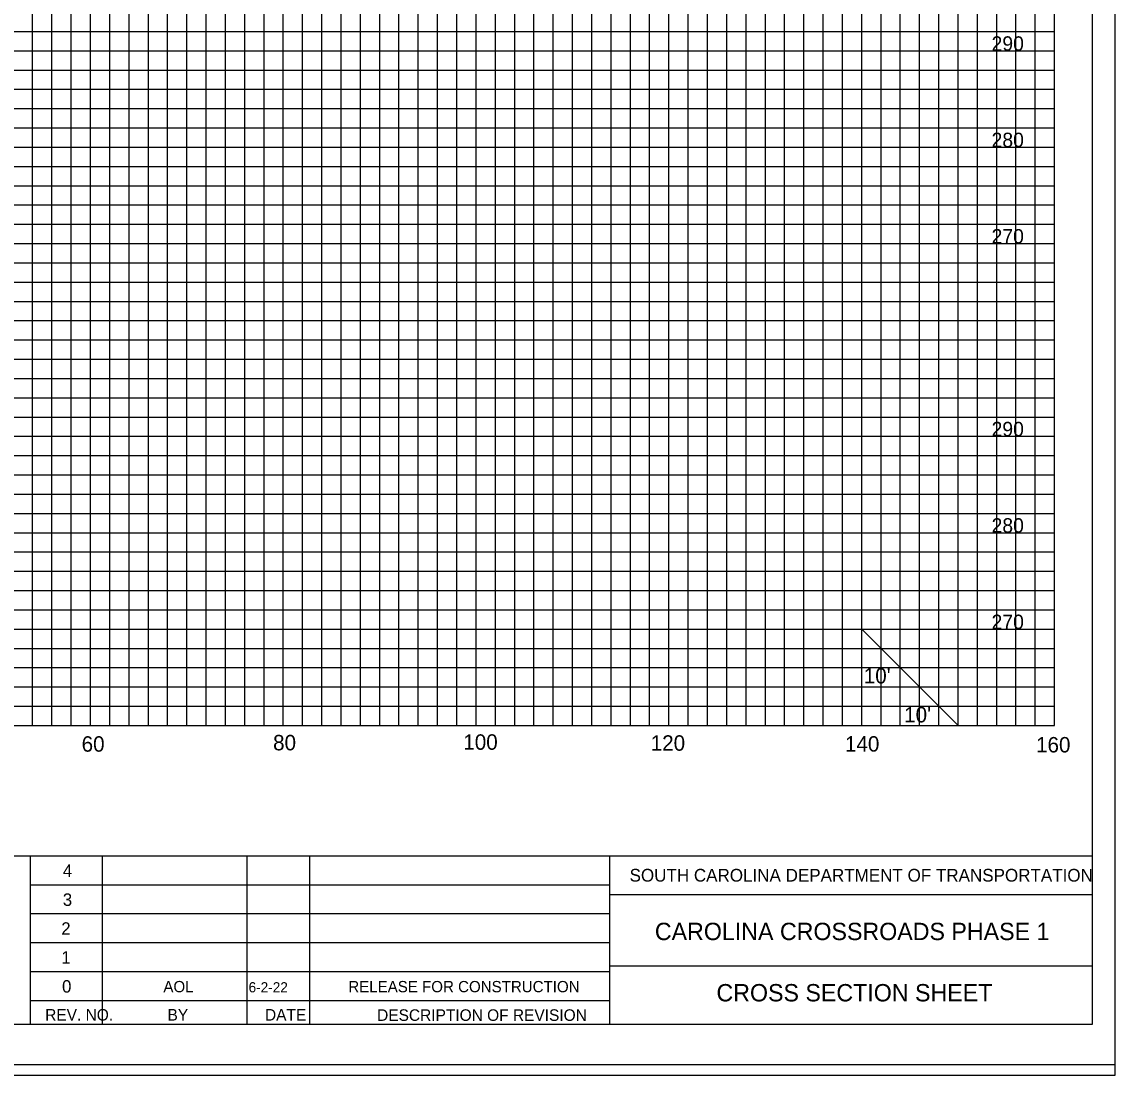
# Model space of a CAD drawing. Extents: x 967 to 1326, y 964 to 3704.
# Drawn here: x 1212.9 to 1326.3, y 2083.7 to 2193 of the extents above; entities that cross this region are included whole.
import ezdxf

# ---------------------------------------------------------------- set-up
doc = ezdxf.new("R2010")
doc.units = 0
for name, color, linetype in [('Default', 7, 'Continuous'), ('RD_SHT_Bndy', 7, 'Continuous'), ('RD_SHT_IplotShp', 7, 'Continuous'), ('RD_SHT_Misc1', 7, 'Continuous'), ('RD_SHT_MjGrid', 7, 'Continuous'), ('RD_SHT_MnGrid', 7, 'Continuous'), ('RD_SHT_TX', 7, 'Continuous'), ('RD_XS_TX_Station', 7, 'Continuous')]:
    doc.layers.add(name, color=color, linetype=linetype)

msp = doc.modelspace()

# ---------------------------------------------------------------- linework, layer by layer
at = {"layer": 'RD_SHT_Bndy'}
for p, q in [((1323.89, 2298.46), (1323.89, 2088.98)), ((996.11, 2106.49), (1323.89, 2106.49)), ((1213.76, 2088.94), (1213.76, 2106.49)), ((1221.26, 2088.95), (1221.26, 2106.48)), ((1236.26, 2088.95), (1236.26, 2106.48)), ((1242.76, 2088.95), (1242.76, 2106.48)), ((1273.88, 2088.98), (1273.88, 2106.49)), ((1213.76, 2103.48), (1273.88, 2103.48)), ((1323.93, 2102.43), (1273.88, 2102.43)), ((1213.76, 2100.48), (1273.88, 2100.48)), ((1213.76, 2097.48), (1273.88, 2097.48)), ((1323.89, 2095.04), (1273.88, 2095.04)), ((1213.76, 2094.48), (1273.88, 2094.48)), ((1213.76, 2091.48), (1273.88, 2091.48)), ((1323.89, 2088.98), (996.11, 2088.98))]:
    msp.add_line(p, q, dxfattribs=at)
at = {"layer": 'RD_SHT_IplotShp'}
for points in [[(967.41, 2083.72), (1326.28, 2083.72), (1326.28, 2303.72), (967.41, 2303.72)], [(988.52, 2084.84), (1326.28, 2084.84), (1326.28, 2302.6), (988.52, 2302.6)]]:
    msp.add_lwpolyline(points, close=True, dxfattribs=at)
at = {"layer": 'RD_SHT_MjGrid'}
for p, q in [((1220, 2120), (1220, 2290)), ((1230, 2120), (1230, 2290)), ((1240, 2120), (1240, 2290)), ((1250, 2120), (1250, 2290)), ((1260, 2120), (1260, 2290)), ((1270, 2120), (1270, 2290)), ((1280, 2120), (1280, 2290)), ((1290, 2120), (1290, 2290)), ((1300, 2120), (1300, 2290)), ((1310, 2120), (1310, 2290)), ((1320, 2120), (1320, 2290)), ((1000, 2190), (1320, 2190)), ((1000, 2180), (1320, 2180)), ((1000, 2170), (1320, 2170)), ((1000, 2160), (1320, 2160)), ((1000, 2150), (1320, 2150)), ((1000, 2140), (1320, 2140)), ((1000, 2130), (1320, 2130)), ((1000, 2120), (1320, 2120))]:
    msp.add_line(p, q, dxfattribs=at)
at = {"layer": 'RD_SHT_MnGrid'}
for p, q in [((1214, 2120), (1214, 2290)), ((1216, 2120), (1216, 2290)), ((1218, 2120), (1218, 2290)), ((1222, 2120), (1222, 2290)), ((1224, 2120), (1224, 2290)), ((1226, 2120), (1226, 2290)), ((1228, 2120), (1228, 2290)), ((1232, 2120), (1232, 2290)), ((1234, 2120), (1234, 2290)), ((1236, 2120), (1236, 2290)), ((1238, 2120), (1238, 2290)), ((1242, 2120), (1242, 2290)), ((1244, 2120), (1244, 2290)), ((1246, 2120), (1246, 2290)), ((1248, 2120), (1248, 2290)), ((1252, 2120), (1252, 2290)), ((1254, 2120), (1254, 2290)), ((1256, 2120), (1256, 2290)), ((1258, 2120), (1258, 2290)), ((1262, 2120), (1262, 2290)), ((1264, 2120), (1264, 2290)), ((1266, 2120), (1266, 2290)), ((1268, 2120), (1268, 2290)), ((1272, 2120), (1272, 2290)), ((1274, 2120), (1274, 2290)), ((1276, 2120), (1276, 2290)), ((1278, 2120), (1278, 2290)), ((1282, 2120), (1282, 2290)), ((1284, 2120), (1284, 2290)), ((1286, 2120), (1286, 2290)), ((1288, 2120), (1288, 2290)), ((1292, 2120), (1292, 2290)), ((1294, 2120), (1294, 2290)), ((1296, 2120), (1296, 2290)), ((1298, 2120), (1298, 2290)), ((1302, 2120), (1302, 2290)), ((1304, 2120), (1304, 2290)), ((1306, 2120), (1306, 2290)), ((1308, 2120), (1308, 2290)), ((1312, 2120), (1312, 2290)), ((1314, 2120), (1314, 2290)), ((1316, 2120), (1316, 2290)), ((1318, 2120), (1318, 2290)), ((1000, 2192), (1320, 2192)), ((1000, 2188), (1320, 2188)), ((1000, 2186), (1320, 2186)), ((1000, 2184), (1320, 2184)), ((1000, 2182), (1320, 2182)), ((1000, 2178), (1320, 2178)), ((1000, 2176), (1320, 2176)), ((1000, 2174), (1320, 2174)), ((1000, 2172), (1320, 2172)), ((1000, 2168), (1320, 2168)), ((1000, 2166), (1320, 2166)), ((1000, 2164), (1320, 2164)), ((1000, 2162), (1320, 2162)), ((1000, 2158), (1320, 2158)), ((1000, 2156), (1320, 2156)), ((1000, 2154), (1320, 2154)), ((1000, 2152), (1320, 2152)), ((1000, 2148), (1320, 2148)), ((1000, 2146), (1320, 2146)), ((1000, 2144), (1320, 2144)), ((1000, 2142), (1320, 2142)), ((1000, 2138), (1320, 2138)), ((1000, 2136), (1320, 2136)), ((1000, 2134), (1320, 2134)), ((1000, 2132), (1320, 2132)), ((1000, 2128), (1320, 2128)), ((1000, 2126), (1320, 2126)), ((1000, 2124), (1320, 2124)), ((1000, 2122), (1320, 2122))]:
    msp.add_line(p, q, dxfattribs=at)
at = {"layer": 'RD_SHT_TX'}
msp.add_line((1300, 2130), (1310, 2120), dxfattribs=at)
at = {"layer": 'RD_XS_TX_Station'}
msp.add_lwpolyline([(967.41, 2083.72), (1326.28, 2083.72), (1326.28, 2303.72), (967.41, 2303.72)], close=True, dxfattribs=at)

# ---------------------------------------------------------------- texts
at = {"layer": 'Default'}
for s, p in [('290', (1313.47, 2190)), ('280', (1313.47, 2180)), ('270', (1313.47, 2170)), ('290', (1313.47, 2150)), ('280', (1313.47, 2140)), ('270', (1313.47, 2130))]:
    msp.add_text(s, height=1.5, dxfattribs=at).set_placement(p)
at = {"layer": 'RD_SHT_Misc1'}
for s, height, p in [('AOL', 1.17, (1227.56, 2092.32)), ('RELEASE FOR CONSTRUCTION', 1.17, (1246.74, 2092.32)), ('6-2-22', 1.053, (1236.4, 2092.31))]:
    msp.add_text(s, height=height, dxfattribs=at).set_placement(p)
at = {"layer": 'RD_SHT_TX'}
for s, height, p in [("10'", 1.6, (1300.21, 2124.36)), ("10'", 1.6, (1304.4, 2120.32)), ('60', 1.6, (1219.08, 2117.28)), ('80', 1.6, (1238.94, 2117.42)), ('100', 1.6, (1258.67, 2117.48)), ('120', 1.6, (1278.11, 2117.38)), ('140', 1.6, (1298.26, 2117.29)), ('160', 1.6, (1318.08, 2117.2)), ('4', 1.3, (1217.13, 2104.28)), ('SOUTH CAROLINA DEPARTMENT OF TRANSPORTATION', 1.32, (1275.92, 2103.8)), ('3', 1.3, (1217.13, 2101.28)), ('2', 1.3, (1216.97, 2098.28)), ('1', 1.3, (1216.97, 2095.28)), ('0', 1.3, (1217.05, 2092.28)), ('REV. NO.', 1.2, (1215.3, 2089.38)), ('BY', 1.2, (1227.99, 2089.38)), ('DATE', 1.2, (1238.1, 2089.38)), ('DESCRIPTION OF REVISION', 1.2, (1249.73, 2089.35))]:
    msp.add_text(s, height=height, dxfattribs=at).set_placement(p)
for s, p in [('CAROLINA CROSSROADS PHASE 1', (1278.54, 2097.73)), ('CROSS SECTION SHEET', (1284.93, 2091.37))]:
    msp.add_text(s, height=1.8, rotation=0, dxfattribs=at).set_placement(p)

doc.saveas('drawing.dxf')
